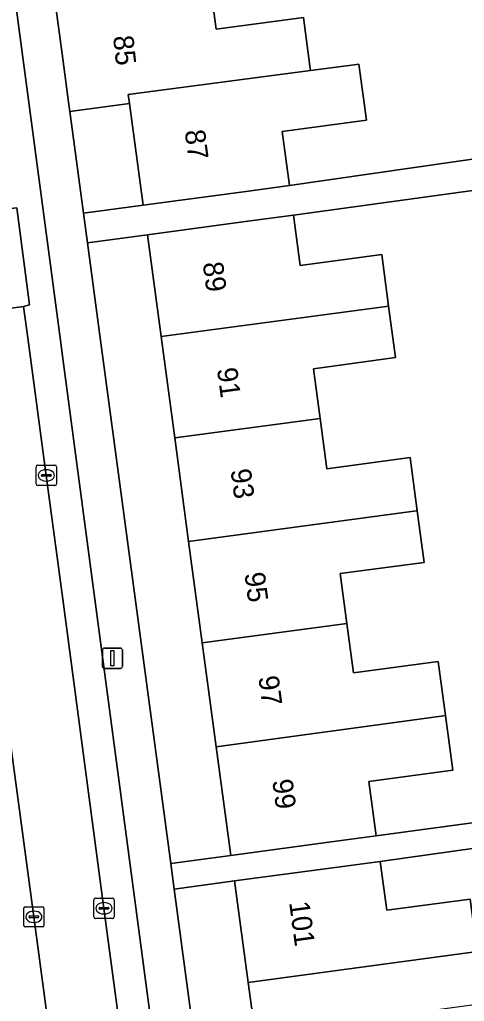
# Model space of a CAD drawing. Extents: x 163147 to 163550, y 380933 to 381639.
# Drawn here: x 163497.87 to 163519.82, y 381217.29 to 381265.69 of the extents above; entities that cross this region are included whole.
import ezdxf

# ---------------------------------------------------------------- set-up
doc = ezdxf.new("R2010")
doc.units = 0
for name, color, linetype in [('IMGEO_Erf', 7, 'Continuous'), ('IMGEO_Kolk', 7, 'Continuous'), ('IMGEO_Lichtmast', 7, 'Continuous'), ('IMGEO_Pand', 7, 'Continuous'), ('IMGEO_Pand_nummerreeks', 7, 'Continuous'), ('IMGEO_Parkeervlak_open', 7, 'Continuous'), ('IMGEO_Rijbaan_lokaal_open', 7, 'Continuous'), ('IMGEO_Voetpad_open', 7, 'Continuous')]:
    doc.layers.add(name, color=color, linetype=linetype)

msp = doc.modelspace()

# ---------------------------------------------------------------- linework, layer by layer
at = {"layer": 'IMGEO_Erf'}
for points in [[(163507.236, 381267.699), (163507.569, 381265.224), (163511.874, 381265.803), (163512.212, 381263.288), (163512.226, 381263.181), (163514.374, 381263.463), (163514.609, 381263.494), (163514.981, 381260.734), (163510.829, 381260.175), (163511.187, 381257.513), (163529.461, 381260.141)], [(163529.68, 381258.575), (163511.38, 381256.054), (163511.714, 381253.572), (163515.739, 381254.113), (163516.081, 381251.569), (163516.292, 381250), (163516.423, 381249.026), (163512.367, 381248.481), (163512.697, 381246.027), (163513.03, 381243.549), (163517.135, 381244.101), (163517.488, 381241.478), (163517.83, 381238.933), (163513.69, 381238.376), (163514.021, 381235.914), (163514.348, 381233.488), (163518.529, 381234.05), (163518.889, 381231.376), (163519.251, 381228.682), (163515.098, 381228.123), (163515.459, 381225.442), (163535.898, 381228.212)], [(163537.213, 381216.868), (163537.063, 381218.145), (163534.336, 381217.777), (163533.89, 381221.604), (163533.3, 381226.66), (163515.663, 381224.189), (163515.989, 381221.775), (163520.096, 381222.329), (163520.445, 381219.741), (163520.789, 381217.19)]]:
    msp.add_lwpolyline(points, dxfattribs=at)
for points in [[(163503.286, 381261.566), (163500.348, 381261.17), (163501.023, 381256.146), (163503.962, 381256.541)], [(163505.522, 381245.067), (163504.849, 381250.067), (163504.174, 381255.085), (163501.219, 381254.688), (163501.849, 381250), (163505.332, 381224.08), (163508.291, 381224.478), (163507.569, 381229.843), (163506.881, 381234.959), (163506.207, 381239.968)], [(163509.837, 381213.166), (163509.156, 381218.215), (163508.481, 381223.221), (163505.501, 381222.821), (163509.584, 381192.438), (163512.578, 381192.84), (163511.88, 381198.018), (163511.199, 381203.067), (163510.518, 381208.118)]]:
    msp.add_lwpolyline(points, close=True, dxfattribs=at)
at = {"layer": 'IMGEO_Kolk'}
for p, q in [((163498.686, 381242.797), (163498.686, 381243.649)), ((163498.761, 381243.723), (163499.613, 381243.723)), ((163499.174, 381243.503), (163499.199, 381243.503)), ((163499.687, 381243.649), (163499.687, 381242.797)), ((163498.945, 381243.217), (163498.945, 381243.229)), ((163499.383, 381243.18), (163498.985, 381243.18)), ((163498.988, 381243.266), (163499.386, 381243.266)), ((163499.197, 381242.943), (163499.172, 381242.943)), ((163499.429, 381243.229), (163499.429, 381243.217)), ((163499.613, 381242.723), (163498.761, 381242.723)), ((163501.532, 381221.448), (163501.532, 381222.3)), ((163501.607, 381222.374), (163502.459, 381222.374)), ((163502.02, 381222.154), (163502.045, 381222.154)), ((163502.533, 381222.3), (163502.533, 381221.448)), ((163498.071, 381221.028), (163498.071, 381221.88)), ((163498.146, 381221.954), (163498.998, 381221.954)), ((163498.559, 381221.734), (163498.584, 381221.734)), ((163499.072, 381221.88), (163499.072, 381221.028)), ((163501.791, 381221.868), (163501.791, 381221.88)), ((163502.229, 381221.831), (163501.831, 381221.831)), ((163501.834, 381221.917), (163502.232, 381221.917)), ((163502.275, 381221.88), (163502.275, 381221.868)), ((163498.33, 381221.448), (163498.33, 381221.46)), ((163498.768, 381221.411), (163498.37, 381221.411)), ((163498.373, 381221.497), (163498.771, 381221.497)), ((163498.582, 381221.174), (163498.557, 381221.174)), ((163498.814, 381221.46), (163498.814, 381221.448)), ((163502.459, 381221.374), (163501.607, 381221.374)), ((163502.043, 381221.594), (163502.018, 381221.594)), ((163498.998, 381220.954), (163498.146, 381220.954))]:
    msp.add_line(p, q, dxfattribs=at)
for points in [[(163498.686, 381242.797), (163498.686, 381243.649)], [(163498.761, 381243.723), (163499.613, 381243.723)], [(163499.687, 381243.649), (163499.687, 381242.797)], [(163499.613, 381242.723), (163498.761, 381242.723)], [(163501.532, 381221.448), (163501.532, 381222.3)], [(163501.607, 381222.374), (163502.459, 381222.374)], [(163502.533, 381222.3), (163502.533, 381221.448)], [(163498.071, 381221.028), (163498.071, 381221.88)], [(163498.146, 381221.954), (163498.998, 381221.954)], [(163499.072, 381221.88), (163499.072, 381221.028)], [(163502.459, 381221.374), (163501.607, 381221.374)], [(163498.998, 381220.954), (163498.146, 381220.954)]]:
    msp.add_lwpolyline(points, dxfattribs=at)
for centre, radius, start, end in [((163498.763, 381243.647), 0.0765, 91.552, 178.448), ((163498.763, 381243.647), 0.0765, 91.552, 178.448), ((163499.611, 381243.647), 0.0765, 1.552, 88.448), ((163499.611, 381243.647), 0.0765, 1.552, 88.448), ((163498.985, 381243.226), 0.0403, 85.8775, 175.7526), ((163498.982, 381243.216), 0.0366, 178.938, 274.7102), ((163499.386, 381243.223), 0.043, 264.8664, 352.4533), ((163499.39, 381243.228), 0.0386, 1.7309, 96.639), ((163498.763, 381242.799), 0.0765, 181.552, 268.448), ((163498.763, 381242.799), 0.0765, 181.552, 268.448), ((163499.611, 381242.799), 0.0765, 271.552, 358.448), ((163499.611, 381242.799), 0.0765, 271.552, 358.448), ((163501.609, 381222.298), 0.0765, 91.552, 178.448), ((163501.609, 381222.298), 0.0765, 91.552, 178.448), ((163502.457, 381222.298), 0.0765, 1.552, 88.448), ((163502.457, 381222.298), 0.0765, 1.552, 88.448), ((163498.148, 381221.878), 0.0765, 91.552, 178.448), ((163498.148, 381221.878), 0.0765, 91.552, 178.448), ((163498.996, 381221.878), 0.0765, 1.552, 88.448), ((163498.996, 381221.878), 0.0765, 1.552, 88.448), ((163501.831, 381221.877), 0.0403, 85.8775, 175.7526), ((163501.828, 381221.867), 0.0366, 178.938, 274.7102), ((163502.232, 381221.874), 0.043, 264.8664, 352.4533), ((163502.236, 381221.879), 0.0386, 1.7309, 96.639), ((163498.37, 381221.457), 0.0403, 85.8775, 175.7526), ((163498.367, 381221.447), 0.0366, 178.938, 274.7102), ((163498.771, 381221.454), 0.043, 264.8664, 352.4533), ((163498.775, 381221.459), 0.0386, 1.7309, 96.639), ((163501.609, 381221.45), 0.0765, 181.552, 268.448), ((163501.609, 381221.45), 0.0765, 181.552, 268.448), ((163502.457, 381221.45), 0.0765, 271.552, 358.448), ((163502.457, 381221.45), 0.0765, 271.552, 358.448), ((163498.148, 381221.03), 0.0765, 181.552, 268.448), ((163498.148, 381221.03), 0.0765, 181.552, 268.448), ((163498.996, 381221.03), 0.0765, 271.552, 358.448), ((163498.996, 381221.03), 0.0765, 271.552, 358.448)]:
    msp.add_arc(centre, radius, start, end, dxfattribs=at)
for centre, major_axis, ratio, start_param, end_param in [((163499.173, 381243.223), (-0.387, 0.002), 0.722429, 4.712389, 7.853982), ((163499.198, 381243.223), (-0.39, 0.002), 0.717154, 1.570796, 4.712389), ((163502.019, 381221.874), (-0.387, 0.002), 0.722429, 4.712389, 7.853982), ((163502.044, 381221.874), (-0.39, 0.002), 0.717154, 1.570796, 4.712389), ((163498.558, 381221.454), (-0.387, 0.002), 0.722429, 4.712389, 7.853982), ((163498.583, 381221.454), (-0.39, 0.002), 0.717154, 1.570796, 4.712389)]:
    msp.add_ellipse(centre, major_axis=major_axis, ratio=ratio, start_param=start_param, end_param=end_param, dxfattribs=at)
at = {"layer": 'IMGEO_Lichtmast'}
for p, q in [((163502.055, 381234.705), (163502.845, 381234.705)), ((163502.845, 381234.705), (163502.055, 381234.705)), ((163501.955, 381233.805), (163501.955, 381234.605)), ((163501.955, 381234.605), (163501.955, 381233.805)), ((163502.945, 381234.605), (163502.945, 381233.805)), ((163502.945, 381233.805), (163502.945, 381234.605)), ((163502.845, 381233.705), (163502.055, 381233.705)), ((163502.055, 381233.705), (163502.845, 381233.705))]:
    msp.add_line(p, q, dxfattribs=at)
msp.add_lwpolyline([(163502.375, 381234.58), (163502.525, 381234.58), (163502.525, 381233.83), (163502.375, 381233.83), (163502.375, 381234.58)], dxfattribs=at)
for centre, start, end in [((163502.055, 381234.605), 90, 180), ((163502.055, 381234.605), 90, 180), ((163502.845, 381234.605), 0, 90), ((163502.845, 381234.605), 360, 90), ((163502.055, 381233.805), 180, 270), ((163502.055, 381233.805), 180, 270), ((163502.845, 381233.805), 270, 0), ((163502.845, 381233.805), 270, 0)]:
    msp.add_arc(centre, 0.1, start, end, dxfattribs=at)
at = {"layer": 'IMGEO_Pand'}
for points in [[(163511.874, 381265.803), (163507.569, 381265.224), (163507.236, 381267.699), (163500.119, 381266.756), (163499.606, 381266.687), (163500, 381263.757), (163500.288, 381261.616), (163500.348, 381261.17), (163503.286, 381261.566), (163503.227, 381262.001), (163512.226, 381263.181), (163512.212, 381263.288)], [(163514.981, 381260.734), (163514.609, 381263.494), (163514.374, 381263.463), (163512.226, 381263.181), (163503.227, 381262.001), (163503.286, 381261.566), (163503.962, 381256.541), (163508.918, 381257.208), (163511.187, 381257.513), (163510.829, 381260.175)], [(163504.849, 381250.067), (163515.966, 381251.554), (163516.081, 381251.569), (163515.739, 381254.113), (163511.714, 381253.572), (163511.38, 381256.054), (163509.13, 381255.751), (163504.174, 381255.085)], [(163512.697, 381246.027), (163512.367, 381248.481), (163516.423, 381249.026), (163516.292, 381250), (163516.081, 381251.569), (163515.966, 381251.554), (163504.849, 381250.067), (163505.522, 381245.067)], [(163512.697, 381246.027), (163505.522, 381245.067), (163506.207, 381239.968), (163517.317, 381241.455), (163517.488, 381241.478), (163517.135, 381244.101), (163513.03, 381243.549)], [(163514.021, 381235.914), (163513.69, 381238.376), (163517.83, 381238.933), (163517.488, 381241.478), (163517.317, 381241.455), (163506.207, 381239.968), (163506.881, 381234.959)], [(163514.021, 381235.914), (163506.881, 381234.959), (163507.569, 381229.843), (163518.668, 381231.346), (163518.889, 381231.376), (163518.529, 381234.05), (163514.348, 381233.488)], [(163518.889, 381231.376), (163518.668, 381231.346), (163507.569, 381229.843), (163508.291, 381224.478), (163513.247, 381225.145), (163515.459, 381225.442), (163515.098, 381228.123), (163519.251, 381228.682)], [(163520.445, 381219.741), (163520.096, 381222.329), (163515.989, 381221.775), (163515.663, 381224.189), (163513.437, 381223.889), (163508.481, 381223.221), (163509.156, 381218.215), (163520.224, 381219.711)], [(163517.005, 381214.135), (163516.668, 381216.634), (163520.789, 381217.19), (163520.445, 381219.741), (163520.224, 381219.711), (163509.156, 381218.215), (163509.837, 381213.166), (163516.87, 381214.117)]]:
    msp.add_lwpolyline(points, close=True, dxfattribs=at)
at = {"layer": 'IMGEO_Parkeervlak_open'}
for points in [[(163490.584, 381309.465), (163490.402, 381309.443), (163490.846, 381305.849), (163493.759, 381284.035), (163496.541, 381263.222), (163497.43, 381256.373), (163497.739, 381256.415), (163498.362, 381251.625), (163498.069, 381251.55), (163498.277, 381250), (163499.186, 381243.223), (163500, 381237.114), (163502.031, 381221.873), (163503.782, 381208.782)], [(163504.96, 381211.766), (163500, 381248.982), (163499.864, 381250), (163492.278, 381306.923)], [(163503.549, 381184.23), (163501.36, 381200.568), (163500, 381210.764), (163498.574, 381221.455), (163495.662, 381242.977), (163494.749, 381250), (163494.609, 381251.077), (163494.305, 381251.042), (163493.658, 381255.873), (163494.08, 381255.92), (163493.013, 381263.045), (163490.358, 381282.994), (163490.149, 381285.047)]]:
    msp.add_lwpolyline(points, dxfattribs=at)
at = {"layer": 'IMGEO_Rijbaan_lokaal_open'}
for points in [[(163494.08, 381255.92), (163493.658, 381255.873), (163494.305, 381251.042), (163494.609, 381251.077), (163498.069, 381251.55), (163498.362, 381251.625), (163497.739, 381256.415), (163497.43, 381256.373)], [(163506.998, 381184.771), (163504.806, 381200.993), (163503.796, 381208.674), (163503.782, 381208.782), (163502.031, 381221.873), (163500, 381237.114), (163499.186, 381243.223), (163498.277, 381250), (163498.069, 381251.55), (163494.609, 381251.077), (163494.749, 381250), (163495.662, 381242.977), (163498.574, 381221.455), (163500, 381210.764), (163501.36, 381200.568), (163503.549, 381184.23)]]:
    msp.add_lwpolyline(points, close=True, dxfattribs=at)
at = {"layer": 'IMGEO_Voetpad_open'}
for points in [[(163509.584, 381192.438), (163505.501, 381222.821), (163505.332, 381224.08), (163501.849, 381250), (163501.219, 381254.688), (163501.023, 381256.146), (163500.348, 381261.17), (163500.288, 381261.616), (163500, 381263.757), (163499.606, 381266.687), (163500.119, 381266.756), (163500, 381267.641), (163499.434, 381271.845), (163498.8, 381276.56), (163498.287, 381276.491), (163498.238, 381276.858), (163497.556, 381281.923), (163496.878, 381286.909), (163496.679, 381288.37), (163493.134, 381314.437)], [(163492.278, 381306.923), (163499.864, 381250), (163500, 381248.982), (163504.96, 381211.766)]]:
    msp.add_lwpolyline(points, dxfattribs=at)
for points in [[(163529.68, 381258.575), (163532.376, 381258.889), (163532.157, 381260.455), (163529.461, 381260.141), (163511.187, 381257.513), (163508.918, 381257.208), (163503.962, 381256.541), (163501.023, 381256.146), (163501.219, 381254.688), (163504.174, 381255.085), (163509.13, 381255.751), (163511.38, 381256.054)], [(163533.3, 381226.66), (163536.023, 381226.978), (163535.898, 381228.212), (163515.459, 381225.442), (163513.247, 381225.145), (163508.291, 381224.478), (163505.332, 381224.08), (163505.501, 381222.821), (163508.481, 381223.221), (163513.437, 381223.889), (163515.663, 381224.189)]]:
    msp.add_lwpolyline(points, close=True, dxfattribs=at)

# ---------------------------------------------------------------- texts
at = {"layer": 'IMGEO_Pand_nummerreeks'}
for s, rotation, p in [('85', 276.245, (163502.478, 381264.868)), ('87', 277.6602, (163506.011, 381260.208)), ('89', 277.661, (163506.904, 381253.689)), ('91', 277.661, (163507.605, 381248.476)), ('93', 277.661, (163508.277, 381243.487)), ('95', 277.661, (163508.963, 381238.386)), ('97', 277.661, (163509.649, 381233.284)), ('99', 277.661, (163510.335, 381228.183)), ('101', 277.6802, (163511.167, 381222.165))]:
    msp.add_text(s, height=1, rotation=rotation, dxfattribs=at).set_placement(p)

doc.saveas('drawing.dxf')
